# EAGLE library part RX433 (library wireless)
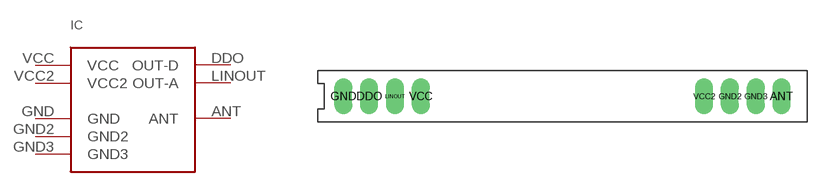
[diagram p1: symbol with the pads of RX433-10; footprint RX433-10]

Designator prefix IC

## RX433  [RX433-10]
ANT  ANT
DDO  OUT-D  out
GND  GND  pwr
GND2  GND2  pwr
GND3  GND3  pwr
LINOUT  OUT-A  out
VCC  VCC  pwr
VCC2  VCC2  pwr

## Footprint RX433-10 (pad centres in mm)
drill 1.016 pad 1.778 long: ANT 43.18,0; DDO 2.54,0; GND 0,0; GND2 38.1,0; GND3 40.64,0; LINOUT 5.08,0; VCC 7.62,0; VCC2 35.56,0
